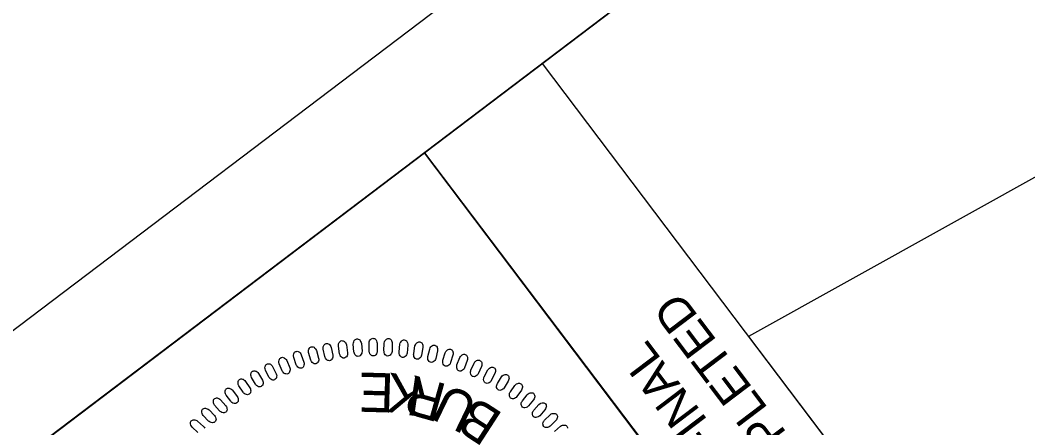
# Model space of a CAD drawing. Extents: x 475599 to 477488, y 499839 to 501843.
# Drawn here: x 475682.3 to 475842.6, y 501228.5 to 501293.3 of the extents above; entities that cross this region are included whole.
import ezdxf

# ---------------------------------------------------------------- set-up
doc = ezdxf.new("R2010")
doc.units = 0
for name, color, linetype in [('Sheet Layout Plan Border', 7, 'Continuous'), ('Sheet PE Seal Cell', 7, 'Continuous'), ('Sheet Plan CELL', 7, 'Continuous'), ('Sheet Plot Border Outside CELL', 7, 'Continuous'), ('Sheet Sticker Exception Certification CELL', 7, 'Continuous')]:
    doc.layers.add(name, color=color, linetype=linetype)

msp = doc.modelspace()

# ---------------------------------------------------------------- linework, layer by layer
at = {"layer": 'Sheet Layout Plan Border'}
msp.add_lwpolyline([(477369.49, 500619.34), (476565.06, 501682.05), (476503.29, 501631.07), (476482.51, 501623.32), (476353.41, 501551.57), (476353.41, 501551.57), (475928.12, 501315.23), (475798.16, 501243.01), (475886.06, 501126.89), (475780.95, 501047.33), (475875.92, 500921.85), (475842.66, 500896.67), (476532.3, 499985.63)], close=True, dxfattribs=at)
at = {"layer": 'Sheet PE Seal Cell'}
for points in [[(475733.09, 501240.26), (475732.92, 501241.48), (475732.92, 501241.7), (475732.95, 501241.84), (475733.04, 501242.03), (475733.12, 501242.15), (475733.22, 501242.25), (475733.32, 501242.3), (475733.42, 501242.34), (475733.54, 501242.33), (475733.66, 501242.32), (475733.77, 501242.28), (475733.89, 501242.19), (475733.96, 501242.12), (475734.05, 501241.98), (475734.13, 501241.82), (475734.18, 501241.66), (475734.37, 501240.42), (475734.37, 501240.25), (475734.35, 501240.1), (475734.28, 501239.93), (475734.19, 501239.78), (475734.11, 501239.69), (475733.96, 501239.6), (475733.81, 501239.56), (475733.66, 501239.58), (475733.55, 501239.61), (475733.41, 501239.69), (475733.27, 501239.84), (475733.17, 501240.01), (475733.13, 501240.14)], [(475735.38, 501240.57), (475735.28, 501241.79), (475735.3, 501242.01), (475735.34, 501242.16), (475735.44, 501242.34), (475735.53, 501242.45), (475735.63, 501242.54), (475735.73, 501242.59), (475735.84, 501242.62), (475735.96, 501242.61), (475736.08, 501242.59), (475736.19, 501242.54), (475736.3, 501242.45), (475736.37, 501242.37), (475736.45, 501242.23), (475736.52, 501242.06), (475736.56, 501241.9), (475736.67, 501240.65), (475736.66, 501240.48), (475736.62, 501240.33), (475736.55, 501240.17), (475736.45, 501240.02), (475736.36, 501239.93), (475736.21, 501239.86), (475736.06, 501239.83), (475735.91, 501239.85), (475735.8, 501239.89), (475735.66, 501239.98), (475735.53, 501240.14), (475735.45, 501240.32), (475735.41, 501240.44)], [(475737.81, 501240.7), (475737.79, 501241.93), (475737.82, 501242.15), (475737.87, 501242.29), (475737.98, 501242.46), (475738.07, 501242.57), (475738.18, 501242.65), (475738.29, 501242.7), (475738.4, 501242.72), (475738.51, 501242.7), (475738.63, 501242.67), (475738.74, 501242.62), (475738.84, 501242.52), (475738.91, 501242.44), (475738.98, 501242.29), (475739.04, 501242.11), (475739.07, 501241.95), (475739.1, 501240.7), (475739.08, 501240.53), (475739.04, 501240.39), (475738.95, 501240.23), (475738.84, 501240.08), (475738.74, 501240), (475738.59, 501239.94), (475738.44, 501239.92), (475738.29, 501239.95), (475738.18, 501240), (475738.05, 501240.1), (475737.93, 501240.27), (475737.86, 501240.44), (475737.83, 501240.57)], [(475740.16, 501240.72), (475740.21, 501241.94), (475740.26, 501242.16), (475740.32, 501242.3), (475740.44, 501242.46), (475740.54, 501242.57), (475740.65, 501242.64), (475740.76, 501242.68), (475740.87, 501242.69), (475740.98, 501242.67), (475741.1, 501242.63), (475741.2, 501242.57), (475741.3, 501242.46), (475741.36, 501242.38), (475741.42, 501242.23), (475741.47, 501242.05), (475741.49, 501241.89), (475741.44, 501240.63), (475741.41, 501240.46), (475741.36, 501240.32), (475741.26, 501240.17), (475741.15, 501240.04), (475741.04, 501239.96), (475740.89, 501239.91), (475740.74, 501239.89), (475740.59, 501239.94), (475740.49, 501239.99), (475740.36, 501240.1), (475740.25, 501240.27), (475740.19, 501240.46), (475740.17, 501240.59)], [(475742.56, 501240.54), (475742.69, 501241.76), (475742.75, 501241.97), (475742.82, 501242.11), (475742.95, 501242.26), (475743.06, 501242.36), (475743.18, 501242.43), (475743.29, 501242.46), (475743.4, 501242.46), (475743.51, 501242.43), (475743.63, 501242.39), (475743.72, 501242.32), (475743.82, 501242.21), (475743.87, 501242.12), (475743.92, 501241.97), (475743.96, 501241.78), (475743.97, 501241.62), (475743.84, 501240.37), (475743.8, 501240.21), (475743.74, 501240.07), (475743.63, 501239.92), (475743.51, 501239.8), (475743.4, 501239.73), (475743.24, 501239.68), (475743.09, 501239.68), (475742.94, 501239.74), (475742.85, 501239.8), (475742.73, 501239.91), (475742.63, 501240.09), (475742.58, 501240.28), (475742.57, 501240.41)], [(475744.89, 501240.28), (475745.09, 501241.49), (475745.17, 501241.69), (475745.24, 501241.82), (475745.38, 501241.97), (475745.5, 501242.06), (475745.62, 501242.12), (475745.73, 501242.15), (475745.85, 501242.15), (475745.95, 501242.11), (475746.06, 501242.06), (475746.16, 501241.98), (475746.24, 501241.87), (475746.29, 501241.78), (475746.33, 501241.62), (475746.36, 501241.43), (475746.35, 501241.27), (475746.15, 501240.03), (475746.1, 501239.87), (475746.03, 501239.74), (475745.92, 501239.59), (475745.78, 501239.48), (475745.67, 501239.41), (475745.51, 501239.38), (475745.36, 501239.39), (475745.22, 501239.45), (475745.12, 501239.52), (475745.01, 501239.64), (475744.92, 501239.82), (475744.89, 501240.01), (475744.88, 501240.15)], [(475726.2, 501238.52), (475725.8, 501239.68), (475725.76, 501239.9), (475725.77, 501240.05), (475725.82, 501240.25), (475725.87, 501240.38), (475725.95, 501240.5), (475726.04, 501240.57), (475726.14, 501240.62), (475726.25, 501240.64), (475726.37, 501240.65), (475726.49, 501240.63), (475726.62, 501240.57), (475726.71, 501240.51), (475726.82, 501240.39), (475726.93, 501240.24), (475727.01, 501240.1), (475727.43, 501238.92), (475727.46, 501238.75), (475727.46, 501238.6), (475727.43, 501238.42), (475727.37, 501238.25), (475727.31, 501238.15), (475727.18, 501238.04), (475727.04, 501237.97), (475726.89, 501237.96), (475726.77, 501237.97), (475726.62, 501238.02), (475726.45, 501238.15), (475726.33, 501238.29), (475726.26, 501238.41)], [(475728.5, 501239.26), (475728.17, 501240.44), (475728.15, 501240.66), (475728.16, 501240.81), (475728.23, 501241.01), (475728.29, 501241.14), (475728.38, 501241.24), (475728.47, 501241.31), (475728.57, 501241.36), (475728.68, 501241.37), (475728.81, 501241.37), (475728.92, 501241.34), (475729.05, 501241.28), (475729.13, 501241.21), (475729.24, 501241.09), (475729.34, 501240.93), (475729.41, 501240.78), (475729.75, 501239.57), (475729.77, 501239.41), (475729.77, 501239.26), (475729.72, 501239.08), (475729.65, 501238.92), (475729.58, 501238.81), (475729.44, 501238.71), (475729.31, 501238.65), (475729.15, 501238.65), (475729.04, 501238.67), (475728.89, 501238.74), (475728.73, 501238.87), (475728.61, 501239.02), (475728.55, 501239.14)], [(475730.75, 501239.8), (475730.49, 501241), (475730.49, 501241.23), (475730.51, 501241.37), (475730.58, 501241.56), (475730.65, 501241.69), (475730.75, 501241.79), (475730.84, 501241.85), (475730.95, 501241.89), (475731.06, 501241.9), (475731.18, 501241.89), (475731.3, 501241.86), (475731.42, 501241.78), (475731.5, 501241.71), (475731.59, 501241.58), (475731.69, 501241.42), (475731.74, 501241.27), (475732.01, 501240.04), (475732.02, 501239.87), (475732.01, 501239.72), (475731.95, 501239.55), (475731.87, 501239.39), (475731.79, 501239.29), (475731.65, 501239.2), (475731.51, 501239.15), (475731.36, 501239.16), (475731.24, 501239.18), (475731.1, 501239.26), (475730.95, 501239.4), (475730.84, 501239.56), (475730.79, 501239.68)], [(475747.15, 501239.82), (475747.44, 501241.01), (475747.52, 501241.22), (475747.6, 501241.34), (475747.75, 501241.48), (475747.87, 501241.56), (475748, 501241.62), (475748.11, 501241.63), (475748.23, 501241.62), (475748.33, 501241.58), (475748.44, 501241.52), (475748.53, 501241.44), (475748.61, 501241.32), (475748.65, 501241.23), (475748.68, 501241.07), (475748.69, 501240.88), (475748.68, 501240.72), (475748.4, 501239.49), (475748.34, 501239.33), (475748.26, 501239.21), (475748.14, 501239.07), (475748, 501238.96), (475747.88, 501238.91), (475747.72, 501238.89), (475747.57, 501238.9), (475747.43, 501238.97), (475747.34, 501239.05), (475747.24, 501239.17), (475747.16, 501239.36), (475747.14, 501239.56), (475747.14, 501239.69)], [(475749.55, 501239.24), (475749.91, 501240.42), (475750.01, 501240.61), (475750.1, 501240.73), (475750.25, 501240.86), (475750.38, 501240.94), (475750.51, 501240.98), (475750.62, 501240.99), (475750.74, 501240.98), (475750.84, 501240.93), (475750.94, 501240.86), (475751.03, 501240.78), (475751.1, 501240.65), (475751.13, 501240.56), (475751.15, 501240.39), (475751.16, 501240.2), (475751.13, 501240.04), (475750.77, 501238.84), (475750.7, 501238.68), (475750.62, 501238.56), (475750.49, 501238.44), (475750.34, 501238.34), (475750.22, 501238.29), (475750.06, 501238.28), (475749.91, 501238.3), (475749.77, 501238.38), (475749.69, 501238.46), (475749.6, 501238.59), (475749.53, 501238.79), (475749.52, 501238.98), (475749.53, 501239.11)], [(475723.97, 501237.55), (475723.5, 501238.68), (475723.45, 501238.9), (475723.44, 501239.05), (475723.48, 501239.25), (475723.53, 501239.39), (475723.6, 501239.51), (475723.68, 501239.58), (475723.78, 501239.64), (475723.89, 501239.67), (475724.01, 501239.69), (475724.13, 501239.67), (475724.26, 501239.62), (475724.35, 501239.57), (475724.47, 501239.46), (475724.59, 501239.32), (475724.68, 501239.18), (475725.17, 501238.02), (475725.21, 501237.86), (475725.22, 501237.71), (475725.2, 501237.53), (475725.15, 501237.36), (475725.1, 501237.24), (475724.97, 501237.13), (475724.84, 501237.05), (475724.69, 501237.03), (475724.57, 501237.04), (475724.42, 501237.08), (475724.24, 501237.19), (475724.11, 501237.33), (475724.03, 501237.44)], [(475751.78, 501238.49), (475752.21, 501239.64), (475752.33, 501239.84), (475752.42, 501239.95), (475752.59, 501240.07), (475752.72, 501240.14), (475752.85, 501240.17), (475752.96, 501240.17), (475753.07, 501240.15), (475753.17, 501240.09), (475753.27, 501240.02), (475753.35, 501239.93), (475753.41, 501239.8), (475753.44, 501239.71), (475753.45, 501239.54), (475753.45, 501239.35), (475753.41, 501239.2), (475752.98, 501238.02), (475752.9, 501237.87), (475752.81, 501237.75), (475752.67, 501237.63), (475752.51, 501237.54), (475752.39, 501237.5), (475752.23, 501237.5), (475752.08, 501237.53), (475751.95, 501237.62), (475751.87, 501237.71), (475751.79, 501237.84), (475751.74, 501238.04), (475751.74, 501238.24), (475751.75, 501238.37)], [(475754, 501237.64), (475754.51, 501238.76), (475754.63, 501238.95), (475754.73, 501239.05), (475754.9, 501239.16), (475755.04, 501239.22), (475755.17, 501239.25), (475755.29, 501239.24), (475755.4, 501239.22), (475755.49, 501239.15), (475755.59, 501239.08), (475755.66, 501238.98), (475755.71, 501238.85), (475755.73, 501238.75), (475755.74, 501238.58), (475755.72, 501238.4), (475755.67, 501238.24), (475755.17, 501237.09), (475755.08, 501236.94), (475754.98, 501236.84), (475754.83, 501236.73), (475754.67, 501236.64), (475754.55, 501236.61), (475754.38, 501236.62), (475754.24, 501236.66), (475754.12, 501236.76), (475754.04, 501236.85), (475753.97, 501236.99), (475753.93, 501237.2), (475753.94, 501237.39), (475753.96, 501237.52)], [(475719.7, 501235.42), (475719.09, 501236.49), (475719.01, 501236.7), (475718.99, 501236.84), (475719, 501237.05), (475719.03, 501237.19), (475719.09, 501237.31), (475719.16, 501237.4), (475719.25, 501237.47), (475719.35, 501237.51), (475719.47, 501237.55), (475719.59, 501237.55), (475719.73, 501237.51), (475719.83, 501237.47), (475719.96, 501237.38), (475720.1, 501237.25), (475720.2, 501237.12), (475720.83, 501236.04), (475720.9, 501235.88), (475720.93, 501235.74), (475720.93, 501235.55), (475720.9, 501235.38), (475720.86, 501235.26), (475720.75, 501235.13), (475720.63, 501235.04), (475720.48, 501235), (475720.37, 501234.99), (475720.21, 501235.01), (475720.02, 501235.1), (475719.87, 501235.22), (475719.78, 501235.32)], [(475721.85, 501236.55), (475721.3, 501237.65), (475721.24, 501237.86), (475721.22, 501238.01), (475721.25, 501238.21), (475721.29, 501238.35), (475721.35, 501238.47), (475721.43, 501238.56), (475721.52, 501238.62), (475721.63, 501238.66), (475721.75, 501238.68), (475721.87, 501238.67), (475722.01, 501238.63), (475722.1, 501238.59), (475722.22, 501238.48), (475722.36, 501238.35), (475722.45, 501238.21), (475723.01, 501237.09), (475723.07, 501236.93), (475723.09, 501236.78), (475723.08, 501236.6), (475723.04, 501236.43), (475722.99, 501236.31), (475722.87, 501236.19), (475722.75, 501236.1), (475722.6, 501236.07), (475722.48, 501236.07), (475722.32, 501236.1), (475722.14, 501236.2), (475722, 501236.34), (475721.92, 501236.44)], [(475756.12, 501236.61), (475756.69, 501237.69), (475756.83, 501237.87), (475756.94, 501237.97), (475757.12, 501238.07), (475757.25, 501238.12), (475757.39, 501238.14), (475757.5, 501238.13), (475757.61, 501238.09), (475757.7, 501238.02), (475757.79, 501237.94), (475757.86, 501237.84), (475757.9, 501237.7), (475757.92, 501237.6), (475757.91, 501237.44), (475757.88, 501237.25), (475757.82, 501237.1), (475757.24, 501235.98), (475757.15, 501235.84), (475757.04, 501235.74), (475756.89, 501235.64), (475756.72, 501235.57), (475756.6, 501235.55), (475756.43, 501235.57), (475756.29, 501235.62), (475756.18, 501235.72), (475756.11, 501235.82), (475756.04, 501235.96), (475756.02, 501236.17), (475756.04, 501236.36), (475756.07, 501236.49)], [(475717.74, 501234.14), (475717.06, 501235.17), (475716.97, 501235.37), (475716.94, 501235.52), (475716.94, 501235.72), (475716.96, 501235.86), (475717.01, 501235.99), (475717.07, 501236.08), (475717.15, 501236.16), (475717.26, 501236.21), (475717.37, 501236.25), (475717.49, 501236.26), (475717.64, 501236.23), (475717.73, 501236.2), (475717.87, 501236.11), (475718.02, 501235.99), (475718.13, 501235.87), (475718.83, 501234.83), (475718.9, 501234.68), (475718.94, 501234.53), (475718.95, 501234.35), (475718.94, 501234.17), (475718.9, 501234.05), (475718.8, 501233.92), (475718.69, 501233.82), (475718.54, 501233.77), (475718.43, 501233.75), (475718.27, 501233.76), (475718.07, 501233.84), (475717.92, 501233.95), (475717.82, 501234.04)], [(475758.21, 501235.52), (475758.85, 501236.57), (475758.99, 501236.74), (475759.11, 501236.83), (475759.29, 501236.91), (475759.43, 501236.96), (475759.57, 501236.97), (475759.68, 501236.95), (475759.79, 501236.91), (475759.87, 501236.83), (475759.96, 501236.74), (475760.02, 501236.64), (475760.05, 501236.5), (475760.06, 501236.4), (475760.04, 501236.24), (475760, 501236.05), (475759.94, 501235.9), (475759.29, 501234.83), (475759.18, 501234.69), (475759.07, 501234.6), (475758.91, 501234.51), (475758.75, 501234.45), (475758.62, 501234.43), (475758.46, 501234.46), (475758.32, 501234.52), (475758.21, 501234.63), (475758.15, 501234.73), (475758.09, 501234.88), (475758.08, 501235.09), (475758.11, 501235.28), (475758.15, 501235.4)], [(475715.77, 501232.7), (475715.03, 501233.68), (475714.93, 501233.87), (475714.89, 501234.02), (475714.87, 501234.22), (475714.88, 501234.37), (475714.93, 501234.5), (475714.98, 501234.59), (475715.06, 501234.68), (475715.16, 501234.73), (475715.28, 501234.78), (475715.4, 501234.79), (475715.54, 501234.77), (475715.64, 501234.75), (475715.78, 501234.67), (475715.94, 501234.56), (475716.05, 501234.45), (475716.81, 501233.45), (475716.9, 501233.3), (475716.95, 501233.16), (475716.97, 501232.98), (475716.97, 501232.8), (475716.94, 501232.68), (475716.85, 501232.54), (475716.74, 501232.43), (475716.6, 501232.37), (475716.48, 501232.35), (475716.32, 501232.35), (475716.13, 501232.42), (475715.96, 501232.52), (475715.86, 501232.6)], [(475760.28, 501234.21), (475760.98, 501235.22), (475761.13, 501235.37), (475761.26, 501235.46), (475761.45, 501235.53), (475761.59, 501235.57), (475761.73, 501235.57), (475761.83, 501235.54), (475761.94, 501235.49), (475762.02, 501235.41), (475762.1, 501235.32), (475762.15, 501235.21), (475762.18, 501235.07), (475762.18, 501234.97), (475762.15, 501234.81), (475762.1, 501234.63), (475762.03, 501234.48), (475761.31, 501233.45), (475761.2, 501233.32), (475761.08, 501233.24), (475760.92, 501233.16), (475760.75, 501233.11), (475760.62, 501233.1), (475760.46, 501233.14), (475760.32, 501233.21), (475760.22, 501233.32), (475760.17, 501233.42), (475760.12, 501233.58), (475760.12, 501233.79), (475760.16, 501233.97), (475760.21, 501234.1)], [(475762.19, 501232.79), (475762.96, 501233.75), (475763.12, 501233.9), (475763.25, 501233.97), (475763.45, 501234.04), (475763.59, 501234.06), (475763.73, 501234.05), (475763.83, 501234.02), (475763.93, 501233.97), (475764.01, 501233.88), (475764.08, 501233.78), (475764.13, 501233.67), (475764.15, 501233.53), (475764.15, 501233.43), (475764.11, 501233.27), (475764.04, 501233.09), (475763.96, 501232.95), (475763.18, 501231.96), (475763.06, 501231.85), (475762.94, 501231.76), (475762.77, 501231.7), (475762.59, 501231.66), (475762.47, 501231.65), (475762.31, 501231.7), (475762.18, 501231.78), (475762.09, 501231.91), (475762.04, 501232.01), (475762, 501232.17), (475762.01, 501232.38), (475762.07, 501232.56), (475762.13, 501232.68)], [(475714, 501231.17), (475713.2, 501232.1), (475713.09, 501232.29), (475713.04, 501232.43), (475713.01, 501232.63), (475713.01, 501232.78), (475713.05, 501232.91), (475713.1, 501233.01), (475713.17, 501233.1), (475713.27, 501233.16), (475713.38, 501233.21), (475713.5, 501233.24), (475713.64, 501233.23), (475713.74, 501233.21), (475713.89, 501233.14), (475714.05, 501233.04), (475714.17, 501232.94), (475715, 501231.99), (475715.09, 501231.84), (475715.15, 501231.71), (475715.18, 501231.53), (475715.19, 501231.35), (475715.17, 501231.23), (475715.09, 501231.08), (475714.99, 501230.97), (475714.85, 501230.9), (475714.74, 501230.87), (475714.58, 501230.86), (475714.37, 501230.91), (475714.21, 501231), (475714.1, 501231.08)], [(475764, 501231.29), (475764.83, 501232.2), (475765, 501232.34), (475765.13, 501232.41), (475765.33, 501232.46), (475765.48, 501232.47), (475765.61, 501232.46), (475765.72, 501232.42), (475765.81, 501232.36), (475765.88, 501232.27), (475765.95, 501232.16), (475765.99, 501232.05), (475766, 501231.91), (475765.99, 501231.81), (475765.94, 501231.65), (475765.86, 501231.48), (475765.77, 501231.34), (475764.94, 501230.41), (475764.81, 501230.3), (475764.68, 501230.22), (475764.51, 501230.16), (475764.33, 501230.13), (475764.2, 501230.14), (475764.05, 501230.2), (475763.92, 501230.29), (475763.84, 501230.42), (475763.8, 501230.52), (475763.77, 501230.68), (475763.79, 501230.89), (475763.86, 501231.07), (475763.93, 501231.18)], [(475712.26, 501229.55), (475711.41, 501230.43), (475711.28, 501230.61), (475711.22, 501230.75), (475711.18, 501230.95), (475711.18, 501231.09), (475711.2, 501231.23), (475711.25, 501231.33), (475711.31, 501231.42), (475711.41, 501231.49), (475711.51, 501231.55), (475711.63, 501231.58), (475711.78, 501231.58), (475711.87, 501231.57), (475712.03, 501231.51), (475712.2, 501231.42), (475712.32, 501231.32), (475713.21, 501230.43), (475713.31, 501230.29), (475713.37, 501230.16), (475713.42, 501229.98), (475713.44, 501229.8), (475713.42, 501229.68), (475713.35, 501229.53), (475713.26, 501229.41), (475713.13, 501229.33), (475713.02, 501229.3), (475712.85, 501229.28), (475712.65, 501229.32), (475712.48, 501229.4), (475712.37, 501229.47)], [(475765.73, 501229.69), (475766.61, 501230.55), (475766.79, 501230.68), (475766.93, 501230.74), (475767.13, 501230.77), (475767.27, 501230.78), (475767.41, 501230.76), (475767.51, 501230.71), (475767.6, 501230.64), (475767.66, 501230.55), (475767.73, 501230.44), (475767.76, 501230.33), (475767.76, 501230.18), (475767.74, 501230.08), (475767.68, 501229.93), (475767.6, 501229.76), (475767.5, 501229.63), (475766.6, 501228.75), (475766.47, 501228.65), (475766.34, 501228.58), (475766.16, 501228.54), (475765.98, 501228.52), (475765.86, 501228.53), (475765.7, 501228.6), (475765.58, 501228.7), (475765.51, 501228.83), (475765.47, 501228.94), (475765.45, 501229.1), (475765.49, 501229.3), (475765.57, 501229.48), (475765.65, 501229.59)]]:
    msp.add_lwpolyline(points, close=True, dxfattribs=at)
for points in [[(475710.56, 501227.76), (475709.65, 501228.58), (475709.51, 501228.76), (475709.44, 501228.89), (475709.39, 501229.09), (475709.38, 501229.23), (475709.39, 501229.37), (475709.43, 501229.47), (475709.49, 501229.57), (475709.58, 501229.64), (475709.69, 501229.71), (475709.8, 501229.75), (475709.94, 501229.76), (475710.04, 501229.75), (475710.2, 501229.7), (475710.37, 501229.62), (475710.51, 501229.53), (475711.44, 501228.7), (475711.55, 501228.56), (475711.63, 501228.44)], [(475767.31, 501227.92), (475768.24, 501228.72), (475768.43, 501228.84), (475768.57, 501228.89), (475768.77, 501228.91), (475768.92, 501228.91), (475769.05, 501228.88), (475769.15, 501228.83), (475769.24, 501228.75), (475769.3, 501228.66), (475769.35, 501228.55), (475769.38, 501228.43)]]:
    msp.add_lwpolyline(points, dxfattribs=at)
at = {"layer": 'Sheet Plan CELL'}
for points in [[(475626.94, 501181.67), (476532.26, 499985.63), (477369.47, 500619.35), (476464.15, 501815.36)], [(477369.49, 500619.37), (476532.3, 499985.63), (475747.68, 501022.14), (475867.32, 501112.71), (475746.6, 501272.21), (476464.15, 501815.36)], [(475717.25, 501124.58), (475656.9, 501204.3), (475746.6, 501272.21), (475806.96, 501192.49)]]:
    msp.add_lwpolyline(points, close=True, dxfattribs=at)
at = {"layer": 'Sheet Plot Border Outside CELL'}
msp.add_lwpolyline([(476471.84, 501842.5), (477487.9, 500500.19), (476614.82, 499839.31), (475598.76, 501181.63)], close=True, dxfattribs=at)
at = {"layer": 'Sheet Sticker Exception Certification CELL'}
for p, q in [((475746.6, 501272.21), (475765.34, 501286.4)), ((475746.6, 501272.21), (475765.34, 501286.4)), ((475765.33, 501286.39), (475886.06, 501126.89)), ((475765.33, 501286.39), (475886.06, 501126.89)), ((475867.32, 501112.71), (475746.59, 501272.21)), ((475867.32, 501112.71), (475746.59, 501272.21))]:
    msp.add_line(p, q, dxfattribs=at)

# ---------------------------------------------------------------- texts
at = {"layer": 'Sheet PE Seal Cell'}
for s, rotation, p in [('E', 178.3919, (475741.82, 501237.13)), ('K', 171.5462, (475746.57, 501236.45)), ('R', 164.2712, (475750.42, 501235.32)), ('U', 154.1714, (475755.51, 501233.02)), ('B', 147.0545, (475759.32, 501230.61))]:
    msp.add_text(s, height=6.24, rotation=rotation, dxfattribs=at).set_placement(p)
at = {"layer": 'Sheet Sticker Exception Certification CELL'}
for s, p in [('UNLESS ALL SIGNATURES COMPLETED', (475872.93, 501137.02)), ('UNLESS ALL SIGNATURES COMPLETED', (475872.93, 501137.02)), ('DOCUMENT NOT CONSIDERED FINAL', (475862.85, 501135.75)), ('DOCUMENT NOT CONSIDERED FINAL', (475862.85, 501135.75))]:
    msp.add_text(s, height=5.5, rotation=127.1236, dxfattribs=at).set_placement(p)

doc.saveas('drawing.dxf')
